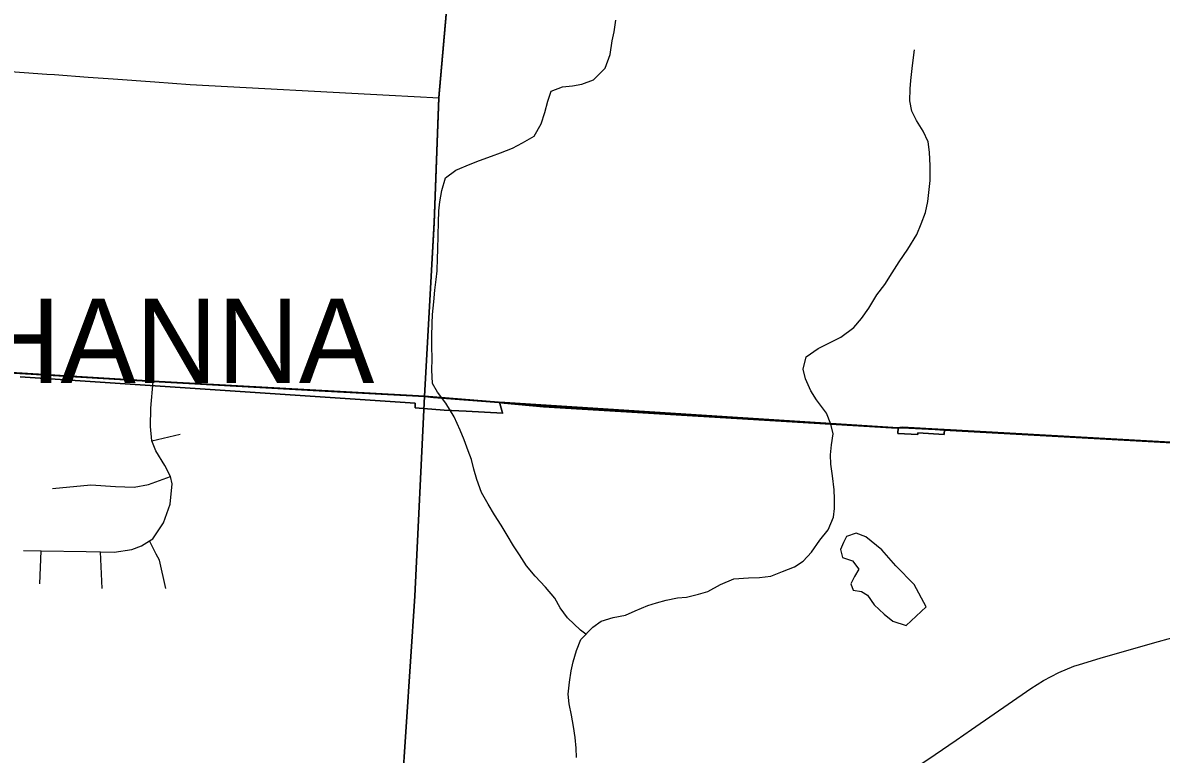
# Model space of a CAD drawing. Extents: x 208586767.6 to 208586821.4, y -134301046.9 to -134301022.9.
# Drawn here: x 208586780.239 to 208586781.515, y -134301027.454 to -134301026.633 of the extents above; entities that cross this region are included whole.
import ezdxf

# ---------------------------------------------------------------- set-up
doc = ezdxf.new("R2010")
doc.units = 0
for name, color, linetype in [('GM_X_City_Street', 7, 'Continuous'), ('GM_X_Corporation', 7, 'Continuous'), ('GM_X_Corporation_Text', 7, 'Continuous'), ('GM_X_County_Road', 7, 'Continuous'), ('GM_X_Minor_Lake', 7, 'Continuous'), ('GM_X_Minor_River', 7, 'Continuous'), ('GM_X_US_Route', 7, 'Continuous')]:
    doc.layers.add(name, color=color, linetype=linetype)

msp = doc.modelspace()

# ---------------------------------------------------------------- linework, layer by layer
at = {"layer": 'GM_X_City_Street'}
for p, q in [((208586780.6892, -134301027.0526), (208586780.6919, -134301027.0035)), ((208586780.6887, -134301027.0627), (208586780.6892, -134301027.0526)), ((208586780.3833, -134301027.1021), (208586780.4151, -134301027.0947)), ((208586780.2575, -134301027.2626), (208586780.2592, -134301027.2255)), ((208586780.3276, -134301027.2677), (208586780.3256, -134301027.2266))]:
    msp.add_line(p, q, dxfattribs=at)
for points in [[(208586780.6919, -134301027.0035), (208586780.7, -134301026.858), (208586780.7054, -134301026.7176), (208586780.7159, -134301026.5984), (208586780.7254, -134301026.4216), (208586780.7519, -134301025.9608), (208586780.7581, -134301025.8575)], [(208586780.2392, -134301027.2252), (208586780.2592, -134301027.2255), (208586780.3096, -134301027.2262), (208586780.3256, -134301027.2266), (208586780.3411, -134301027.227), (208586780.3608, -134301027.2243), (208586780.3715, -134301027.2202), (208586780.3805, -134301027.2146), (208586780.3845, -134301027.2121), (208586780.3965, -134301027.1944), (208586780.4037, -134301027.1733), (208586780.406, -134301027.1506), (208586780.4041, -134301027.1422), (208586780.3978, -134301027.1298), (208586780.3878, -134301027.1135), (208586780.3833, -134301027.1021), (208586780.3817, -134301027.086), (208586780.3822, -134301027.0657), (208586780.3849, -134301027.0357)], [(208586780.6666, -134301027.4534), (208586780.6783, -134301027.2771), (208586780.6887, -134301027.0627)], [(208586780.272, -134301027.1556), (208586780.315, -134301027.1517), (208586780.3424, -134301027.1533), (208586780.3635, -134301027.1543), (208586780.3796, -134301027.1512), (208586780.4041, -134301027.1422)], [(208586780.3988, -134301027.268), (208586780.3917, -134301027.236), (208586780.388, -134301027.2292), (208586780.3805, -134301027.2146)], [(208586780.6279, -134301028.0637), (208586780.6369, -134301027.9137), (208586780.6413, -134301027.8456), (208586780.6462, -134301027.7622), (208586780.6492, -134301027.7167), (208586780.6666, -134301027.4534)]]:
    msp.add_lwpolyline(points, dxfattribs=at)
at = {"layer": 'GM_X_Corporation'}
for points in [[(208586778.0283, -134301024.0407), (208586778.0283, -134301026.8722), (208586778.2066, -134301026.8835), (208586778.3183, -134301026.8891), (208586778.4144, -134301026.8981), (208586778.4744, -134301026.9031), (208586778.5377, -134301026.907), (208586778.5728, -134301026.9094), (208586778.5911, -134301026.9104), (208586778.6265, -134301026.9124), (208586778.6952, -134301026.9163), (208586778.8851, -134301026.9328), (208586779.278, -134301026.9613), (208586779.4919, -134301026.9779), (208586779.719, -134301026.9925), (208586779.8313, -134301027.0004), (208586779.8905, -134301027.0043), (208586780.023, -134301027.0133), (208586780.3847, -134301027.0352), (208586780.6889, -134301027.0521), (208586780.6998, -134301026.8575), (208586780.7052, -134301026.7171), (208586780.7156, -134301026.5978)], [(208586784.8283, -134301024.0407), (208586780.8686, -134301024.0407), (208586780.8608, -134301024.1694), (208586780.8523, -134301024.3094), (208586780.8468, -134301024.4721), (208586780.7938, -134301025.279), (208586780.793, -134301025.292), (208586780.784, -134301025.4293), (208586780.7579, -134301025.857), (208586780.7516, -134301025.9603), (208586780.7252, -134301026.421), (208586780.7156, -134301026.5978), (208586780.7052, -134301026.7171), (208586780.6998, -134301026.8575), (208586780.6889, -134301027.0521), (208586780.7721, -134301027.0589), (208586780.8223, -134301027.0634), (208586781.2193, -134301027.0875), (208586781.2244, -134301027.0871), (208586781.2713, -134301027.0897), (208586781.6677, -134301027.1118)], [(208586780.5786, -134301028.8139), (208586780.6058, -134301028.4074), (208586780.6113, -134301028.3238), (208586780.6133, -134301028.2973), (208586780.6174, -134301028.2483), (208586780.6179, -134301028.2235), (208586780.6206, -134301028.1821), (208586780.6366, -134301027.9132), (208586780.6411, -134301027.845), (208586780.646, -134301027.7617), (208586780.649, -134301027.7162), (208586780.6781, -134301027.2766), (208586780.6889, -134301027.0521), (208586780.3847, -134301027.0352), (208586780.023, -134301027.0133), (208586779.8905, -134301027.0043), (208586779.8313, -134301027.0004), (208586779.719, -134301026.9925), (208586779.4919, -134301026.9779), (208586779.278, -134301026.9613), (208586778.8851, -134301026.9328)], [(208586781.7317, -134301027.1153), (208586781.2721, -134301027.0897), (208586781.2715, -134301027.0951), (208586781.2421, -134301027.0934), (208586781.2419, -134301027.0953), (208586781.2198, -134301027.0939), (208586781.2201, -134301027.0875), (208586780.7729, -134301027.0589), (208586780.7761, -134301027.0697), (208586780.7767, -134301027.0713), (208586780.7355, -134301027.0691), (208586780.7112, -134301027.0678), (208586780.6784, -134301027.0653), (208586780.6784, -134301027.06), (208586780.2357, -134301027.0304)], [(208586780.2357, -134301027.0304), (208586780.6784, -134301027.06), (208586780.6784, -134301027.0653), (208586780.7112, -134301027.0678), (208586780.7355, -134301027.0691), (208586780.7767, -134301027.0713), (208586780.7761, -134301027.0697), (208586780.7729, -134301027.0589), (208586781.2201, -134301027.0875), (208586781.2198, -134301027.0939), (208586781.2419, -134301027.0953), (208586781.2421, -134301027.0934), (208586781.2715, -134301027.0951), (208586781.2721, -134301027.0897), (208586781.7317, -134301027.1153)], [(208586781.6677, -134301027.1118), (208586781.2713, -134301027.0897), (208586781.2244, -134301027.0871), (208586781.2193, -134301027.0875), (208586780.8223, -134301027.0634), (208586780.7721, -134301027.0589), (208586780.6889, -134301027.0521), (208586780.6781, -134301027.2766), (208586780.649, -134301027.7162), (208586780.646, -134301027.7617), (208586780.6411, -134301027.845), (208586780.6366, -134301027.9132), (208586780.6206, -134301028.1821), (208586780.6179, -134301028.2235), (208586780.6174, -134301028.2483), (208586780.6133, -134301028.2973), (208586780.6113, -134301028.3238), (208586780.6058, -134301028.4074), (208586780.5786, -134301028.8139)]]:
    msp.add_lwpolyline(points, dxfattribs=at)
at = {"layer": 'GM_X_County_Road'}
for p, q in [((208586780.2742, -134301026.6915), (208586780.3117, -134301026.6942)), ((208586780.3117, -134301026.6942), (208586780.3399, -134301026.6963)), ((208586780.3399, -134301026.6963), (208586780.3868, -134301026.6997)), ((208586780.6492, -134301026.7146), (208586780.7054, -134301026.7176)), ((208586780.5776, -134301027.0464), (208586780.6892, -134301027.0526)), ((208586780.6892, -134301027.0526), (208586780.6991, -134301027.0535))]:
    msp.add_line(p, q, dxfattribs=at)
for points in [[(208586779.4404, -134301026.6408), (208586779.519, -134301026.6438), (208586779.5549, -134301026.6464), (208586779.6147, -134301026.6503), (208586779.6668, -134301026.6545), (208586779.8083, -134301026.6632), (208586779.9184, -134301026.6693), (208586780.0363, -134301026.6742), (208586780.2657, -134301026.6909), (208586780.2742, -134301026.6915)], [(208586780.3868, -134301026.6997), (208586780.4262, -134301026.7026), (208586780.6492, -134301026.7146)], [(208586778.6954, -134301026.9169), (208586778.8853, -134301026.9333), (208586779.2783, -134301026.9618), (208586779.4921, -134301026.9785), (208586779.7192, -134301026.993), (208586779.8315, -134301027.0009), (208586779.8907, -134301027.0048), (208586780.0232, -134301027.0139), (208586780.3849, -134301027.0357), (208586780.5776, -134301027.0464)], [(208586780.6991, -134301027.0535), (208586780.7723, -134301027.0594), (208586780.7782, -134301027.0599)], [(208586780.7782, -134301027.0599), (208586780.8225, -134301027.064), (208586781.2126, -134301027.0876)], [(208586781.2126, -134301027.0876), (208586781.2195, -134301027.088), (208586781.2246, -134301027.0877), (208586781.2615, -134301027.0897)], [(208586781.2615, -134301027.0897), (208586781.2715, -134301027.0903), (208586781.5878, -134301027.1079)]]:
    msp.add_lwpolyline(points, dxfattribs=at)
at = {"layer": 'GM_X_Minor_Lake'}
for points in [[(208586781.2513, -134301027.2883), (208586781.2381, -134301027.2635), (208586781.2174, -134301027.2425), (208586781.2016, -134301027.2246), (208586781.1838, -134301027.2101), (208586781.1729, -134301027.2058), (208586781.1622, -134301027.2096), (208586781.1587, -134301027.2164), (208586781.1553, -134301027.224), (208586781.1575, -134301027.2331), (208586781.1689, -134301027.2369), (208586781.176, -134301027.2461), (208586781.171, -134301027.2544), (208586781.1668, -134301027.2627), (208586781.1694, -134301027.2696), (208586781.1789, -134301027.2712), (208586781.1857, -134301027.2754), (208586781.1932, -134301027.2861), (208586781.2045, -134301027.2967), (208586781.214, -134301027.3044), (208586781.2291, -134301027.3094)], [(208586781.2291, -134301027.3094), (208586781.2513, -134301027.2883)]]:
    msp.add_lwpolyline(points, dxfattribs=at)
at = {"layer": 'GM_X_Minor_River'}
for points in [[(208586780.87, -134301027.3192), (208586780.864, -134301027.3145), (208586780.8493, -134301027.3007), (208586780.841, -134301027.2897), (208586780.835, -134301027.2786), (208586780.8248, -134301027.2664), (208586780.8131, -134301027.2542), (208586780.8033, -134301027.2424), (208586780.7954, -134301027.2302), (208586780.7887, -134301027.2199), (208586780.7815, -134301027.2081), (208586780.7748, -134301027.197), (208586780.7673, -134301027.1852), (208586780.7605, -134301027.1734), (208586780.753, -134301027.1601), (208586780.7478, -134301027.1456), (208586780.7444, -134301027.1342), (208586780.7415, -134301027.1232), (208586780.7381, -134301027.1133), (208586780.7336, -134301027.1012), (208586780.7288, -134301027.0901), (208586780.7224, -134301027.0753), (208586780.713, -134301027.06), (208586780.7036, -134301027.0475), (208586780.698, -134301027.0379), (208586780.6973, -134301027.0227), (208586780.6974, -134301027.0106), (208586780.6971, -134301026.9958), (208586780.6972, -134301026.9852), (208586780.6977, -134301026.9707), (208586780.6981, -134301026.9605), (208586780.6993, -134301026.9465), (208586780.7006, -134301026.9332), (208586780.7021, -134301026.9214), (208586780.703, -134301026.9116), (208586780.7034, -134301026.8975), (208586780.7039, -134301026.888), (208586780.7044, -134301026.8717), (208586780.7045, -134301026.8573), (208586780.7049, -134301026.8444), (208586780.7061, -134301026.8341), (208586780.7085, -134301026.8216), (208586780.7124, -134301026.8072), (208586780.7242, -134301026.7986), (208586780.7402, -134301026.7918), (208586780.7508, -134301026.7877), (208586780.7641, -134301026.7829), (208586780.774, -134301026.7791), (208586780.7877, -134301026.7739), (208586780.7988, -134301026.7679), (208586780.8121, -134301026.7604), (208586780.8198, -134301026.7468), (208586780.824, -134301026.7339), (208586780.8271, -134301026.7214), (208586780.831, -134301026.71), (208586780.8436, -134301026.7051), (208586780.855, -134301026.7041), (208586780.8652, -134301026.7022), (208586780.8785, -134301026.6974), (208586780.8915, -134301026.6842), (208586780.8973, -134301026.669), (208586780.8993, -134301026.6535), (208586780.9017, -134301026.6436), (208586780.9033, -134301026.6303)], [(208586780.8593, -134301027.4575), (208586780.859, -134301027.4469), (208586780.8579, -134301027.4351), (208586780.8561, -134301027.4226), (208586780.8539, -134301027.4101), (208586780.8513, -134301027.3971), (208586780.8502, -134301027.3865), (208586780.8515, -134301027.3728), (208586780.8534, -134301027.3603), (208586780.8558, -134301027.3501), (208586780.8593, -134301027.3376), (208586780.8643, -134301027.3251), (208586780.8777, -134301027.3111), (208586780.8872, -134301027.3047), (208586780.9005, -134301027.3006), (208586780.9142, -134301027.2977), (208586780.9252, -134301027.2928), (208586780.9393, -134301027.2868), (208586780.9492, -134301027.2839), (208586780.9598, -134301027.2809), (208586780.9728, -134301027.2783), (208586780.9826, -134301027.2776), (208586780.9963, -134301027.2743), (208586781.0066, -134301027.2713), (208586781.0207, -134301027.2634), (208586781.0359, -134301027.257), (208586781.0522, -134301027.256), (208586781.0644, -134301027.2557), (208586781.0773, -134301027.2539), (208586781.0902, -134301027.249), (208586781.1039, -134301027.2434), (208586781.1134, -134301027.2374), (208586781.123, -134301027.2272), (208586781.1322, -134301027.2136), (208586781.1414, -134301027.2022), (208586781.1475, -134301027.1879), (208586781.1487, -134301027.178), (208586781.1488, -134301027.1674), (208586781.1481, -134301027.1571), (208586781.1463, -134301027.1415), (208586781.1445, -134301027.1286), (208586781.1442, -134301027.118), (208586781.1454, -134301027.1066), (208586781.147, -134301027.0945), (208586781.1444, -134301027.0835), (208586781.1395, -134301027.0713), (208586781.1286, -134301027.0564), (208586781.1222, -134301027.0461), (208586781.1163, -134301027.0328), (208586781.1137, -134301027.0218), (208586781.1168, -134301027.0081), (208586781.1305, -134301026.9987), (208586781.1454, -134301026.9912), (208586781.1557, -134301026.986), (208586781.1705, -134301026.9751), (208586781.1789, -134301026.9649), (208586781.187, -134301026.9535), (208586781.1962, -134301026.9384), (208586781.205, -134301026.9267), (208586781.2134, -134301026.9138), (208586781.2211, -134301026.9013), (208586781.231, -134301026.8874), (208586781.241, -134301026.8707), (208586781.246, -134301026.859), (208586781.2507, -134301026.8461), (208586781.2534, -134301026.8336), (208586781.2558, -134301026.8101), (208586781.2559, -134301026.7937), (208586781.2553, -134301026.7786), (208586781.2538, -134301026.7668), (208586781.2482, -134301026.755), (208586781.2407, -134301026.7428), (208586781.2355, -134301026.7325), (208586781.2332, -134301026.7207), (208586781.2333, -134301026.7074), (208586781.2342, -134301026.698), (208586781.2358, -134301026.6847), (208586781.237, -134301026.6752), (208586781.2385, -134301026.6638)]]:
    msp.add_lwpolyline(points, dxfattribs=at)
at = {"layer": 'GM_X_US_Route'}
for points in [[(208586781.2851, -134301027.438), (208586781.3021, -134301027.4262), (208586781.3686, -134301027.3802), (208586781.3831, -134301027.3711), (208586781.4002, -134301027.362), (208586781.4168, -134301027.355), (208586781.4232, -134301027.3532), (208586781.4466, -134301027.3461), (208586781.5051, -134301027.3291), (208586781.5295, -134301027.3226), (208586781.5566, -134301027.314), (208586781.5955, -134301027.2998), (208586781.6074, -134301027.2948), (208586781.611, -134301027.2932)], [(208586781.1998, -134301027.4956), (208586781.2108, -134301027.4883), (208586781.2616, -134301027.4542), (208586781.2851, -134301027.438)]]:
    msp.add_lwpolyline(points, dxfattribs=at)

# ---------------------------------------------------------------- texts
at = {"layer": 'GM_X_Corporation_Text'}
msp.add_text('GAHANNA', height=0.0947, rotation=0, dxfattribs=at).set_placement((208586780.0064, -134301027.0373))

doc.saveas('drawing.dxf')
